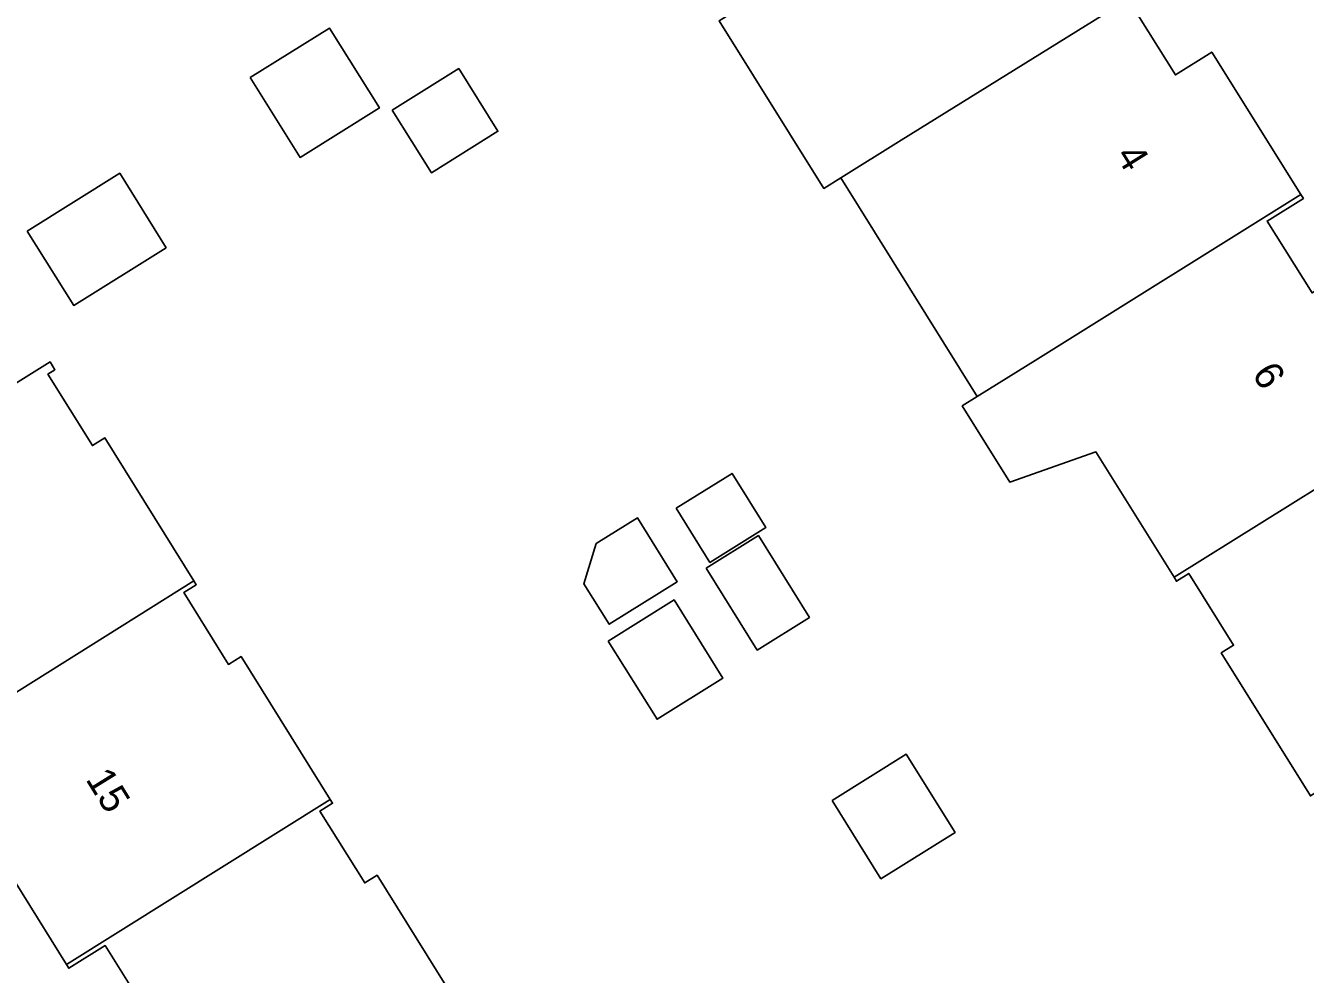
# Model space of a CAD drawing. Extents: x 158835 to 160077, y 386387 to 387778.
# Drawn here: x 159089.27 to 159134.01, y 387005.06 to 387038.21 of the extents above; entities that cross this region are included whole.
import ezdxf

# ---------------------------------------------------------------- set-up
doc = ezdxf.new("R2010")
doc.units = 0
for name, color, linetype in [('IMGEO_Erf', 7, 'Continuous'), ('IMGEO_Pand', 7, 'Continuous'), ('IMGEO_Pand_nummerreeks', 7, 'Continuous')]:
    doc.layers.add(name, color=color, linetype=linetype)

msp = doc.modelspace()

# ---------------------------------------------------------------- linework, layer by layer
at = {"layer": 'IMGEO_Erf'}
for points in [[(159127.9, 387038.991), (159129.471, 387036.486), (159130.74, 387037.282), (159133.86, 387032.308), (159133.945, 387032.172), (159132.676, 387031.376), (159134.247, 387028.871)], [(159134.188, 387011.296), (159131.072, 387016.287), (159131.504, 387016.557), (159129.938, 387019.066), (159129.506, 387018.796), (159129.421, 387018.932), (159126.688, 387023.31), (159123.675, 387022.257), (159122.014, 387024.922), (159122.54, 387025.25), (159117.771, 387032.888), (159117.177, 387032.519), (159113.521, 387038.376)], [(159086.354, 387024.108), (159090.122, 387026.458), (159090.291, 387026.186), (159090.045, 387026.033), (159091.605, 387023.532), (159092.037, 387023.802), (159095.151, 387018.809), (159095.236, 387018.673), (159094.795, 387018.399), (159096.36, 387015.889), (159096.801, 387016.164), (159099.915, 387011.172), (159100, 387011.036), (159099.559, 387010.761), (159101.124, 387008.252), (159101.556, 387008.521), (159104.67, 387003.529)], [(159093.617, 387003.548), (159092.048, 387006.062), (159090.778, 387005.269), (159090.694, 387005.404), (159087.581, 387010.391)]]:
    msp.add_lwpolyline(points, dxfattribs=at)
for points in [[(159097.122, 387036.394), (159099.892, 387038.124), (159101.636, 387035.33), (159098.866, 387033.6)], [(159102.088, 387035.258), (159104.41, 387036.707), (159105.779, 387034.515), (159103.457, 387033.065)], [(159089.326, 387031.029), (159092.559, 387033.047), (159094.181, 387030.449), (159090.948, 387028.431)], [(159112.015, 387021.344), (159113.97, 387022.564), (159115.149, 387020.675), (159113.194, 387019.454)], [(159109.212, 387020.108), (159110.656, 387021.01), (159112.051, 387018.776), (159109.673, 387017.291), (159108.788, 387018.709)], [(159113.063, 387019.253), (159114.888, 387020.392), (159116.674, 387017.53), (159114.85, 387016.391)], [(159109.639, 387016.703), (159111.943, 387018.141), (159113.647, 387015.411), (159111.344, 387013.973)], [(159117.464, 387011.131), (159120.06, 387012.751), (159121.766, 387010.018), (159119.17, 387008.398)]]:
    msp.add_lwpolyline(points, close=True, dxfattribs=at)
at = {"layer": 'IMGEO_Pand'}
for points in [[(159126.003, 387044.947), (159124.729, 387044.145), (159123.151, 387046.65), (159123.397, 387046.805), (159123.226, 387047.077), (159118.985, 387044.429), (159115.226, 387042.082), (159115.395, 387041.811), (159115.641, 387041.964), (159116.658, 387040.335), (159113.521, 387038.376), (159117.177, 387032.519), (159117.771, 387032.888), (159119.886, 387034.203), (159129.085, 387039.923)], [(159130.74, 387037.282), (159129.471, 387036.486), (159127.9, 387038.991), (159129.169, 387039.787), (159129.085, 387039.923), (159119.886, 387034.203), (159117.771, 387032.888), (159122.54, 387025.25), (159124.653, 387026.567), (159133.86, 387032.308)], [(159097.122, 387036.394), (159098.866, 387033.6), (159101.636, 387035.33), (159099.892, 387038.124)], [(159102.088, 387035.258), (159103.457, 387033.065), (159105.779, 387034.515), (159104.41, 387036.707)], [(159089.326, 387031.029), (159090.948, 387028.431), (159094.181, 387030.449), (159092.559, 387033.047)], [(159135.516, 387029.667), (159134.247, 387028.871), (159132.676, 387031.376), (159133.945, 387032.172), (159133.86, 387032.308), (159124.653, 387026.567), (159122.54, 387025.25), (159122.014, 387024.922), (159123.675, 387022.257), (159126.688, 387023.31), (159129.421, 387018.932), (159138.623, 387024.672)], [(159095.151, 387018.809), (159092.037, 387023.802), (159091.605, 387023.532), (159090.045, 387026.033), (159090.291, 387026.186), (159090.122, 387026.458), (159086.354, 387024.108), (159082.111, 387021.461), (159082.28, 387021.19), (159082.526, 387021.343), (159084.102, 387018.817), (159082.83, 387018.024), (159085.933, 387013.032)], [(159129.421, 387018.932), (159129.506, 387018.796), (159129.938, 387019.066), (159131.504, 387016.557), (159131.072, 387016.287), (159134.188, 387011.296), (159143.382, 387017.039), (159140.271, 387022.029), (159139, 387021.237), (159137.437, 387023.744), (159138.708, 387024.536), (159138.623, 387024.672)], [(159112.015, 387021.344), (159113.194, 387019.454), (159115.149, 387020.675), (159113.97, 387022.564)], [(159109.212, 387020.108), (159108.788, 387018.709), (159109.673, 387017.291), (159112.051, 387018.776), (159110.656, 387021.01)], [(159113.063, 387019.253), (159114.85, 387016.391), (159116.674, 387017.53), (159114.888, 387020.392)], [(159099.915, 387011.172), (159096.801, 387016.164), (159096.36, 387015.889), (159094.795, 387018.399), (159095.236, 387018.673), (159095.151, 387018.809), (159085.933, 387013.032), (159086.017, 387012.897), (159087.287, 387013.69), (159088.851, 387011.184), (159087.581, 387010.391), (159090.694, 387005.404)], [(159109.639, 387016.703), (159111.344, 387013.973), (159113.647, 387015.411), (159111.943, 387018.141)], [(159117.464, 387011.131), (159119.17, 387008.398), (159121.766, 387010.018), (159120.06, 387012.751)], [(159099.029, 387000), (159104.67, 387003.529), (159101.556, 387008.521), (159101.124, 387008.252), (159099.559, 387010.761), (159100, 387011.036), (159099.915, 387011.172), (159090.694, 387005.404), (159090.778, 387005.269), (159092.048, 387006.062), (159093.617, 387003.548), (159092.347, 387002.755), (159094.064, 387000), (159095.456, 386997.765)]]:
    msp.add_lwpolyline(points, close=True, dxfattribs=at)

# ---------------------------------------------------------------- texts
at = {"layer": 'IMGEO_Pand_nummerreeks'}
for s, rotation, p in [('4', 301.9995, (159127.356, 387033.672)), ('6', 301.9995, (159132.124, 387026.042)), ('15', 301.7444, (159091.345, 387011.877))]:
    msp.add_text(s, height=1, rotation=rotation, dxfattribs=at).set_placement(p)

doc.saveas('drawing.dxf')
